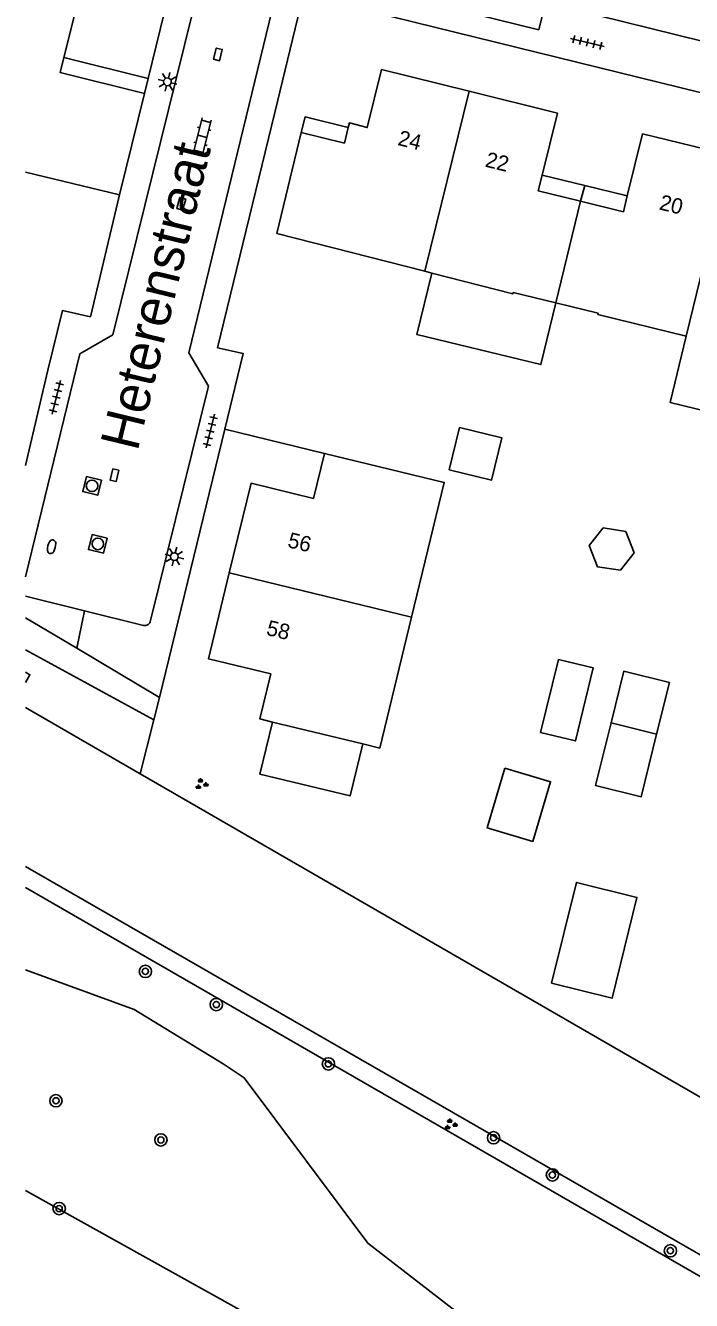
# Model space of a CAD drawing. Extents: x 128000 to 131008, y 398996 to 402500.
# Drawn here: x 128000 to 128043.1, y 399274.1 to 399356.7 of the extents above; entities that cross this region are included whole.
import ezdxf

# ---------------------------------------------------------------- set-up
doc = ezdxf.new("R2010")
doc.units = 0
for name, color, linetype in [('gg-afsc-erfafscheiding', 7, 'Continuous'), ('gg-afsc-muur', 7, 'Continuous'), ('gg-anno-huisnummerreeks BGT', 7, 'Continuous'), ('gg-anno-openbare ruimte label', 7, 'Continuous'), ('gg-bbg-gedigitaliseerde bebouwing', 7, 'Continuous'), ('gg-bbg-gedigitaliseerde bijgebouw', 7, 'Continuous'), ('gg-bbg-hoofdgebouw', 7, 'Continuous'), ('gg-bbg-luifel en loopbrug', 7, 'Continuous'), ('gg-bbg-tussenscheiding', 7, 'Continuous'), ('gg-knt-BGT kruinlijn', 7, 'Continuous'), ('gg-knt-bovenkant onderkant talud', 7, 'Continuous'), ('gg-knt-verharding', 7, 'Continuous'), ('gg-kntw-beschoeiing', 7, 'Continuous'), ('gg-kwrk-uitstroombak niveau min 01', 7, 'Continuous'), ('gt-grn-groengrens', 7, 'Continuous'), ('gt-grn-vlakafsluiter', 7, 'Continuous'), ('gt-grn-weggrens', 7, 'Continuous'), ('gt-symb-boom', 7, 'Continuous'), ('gt-symb-brandkraan', 7, 'Continuous'), ('gt-symb-groenvak', 7, 'Continuous'), ('gt-symb-klinker verharding', 7, 'Continuous'), ('gt-symb-kolk', 7, 'Continuous'), ('gt-symb-lichtmast', 7, 'Continuous'), ('gt-symb-rioolschacht', 7, 'Continuous'), ('gt-symb-tegel verharding', 7, 'Continuous')]:
    doc.layers.add(name, color=color, linetype=linetype)

# ---------------------------------------------------------------- blocks, each defined once
blk = doc.blocks.new('gt0-TEG1')
at = {"layer": 'gt-symb-tegel verharding'}
for p, q in [((-1.125, 0), (1.125, 0)), ((-0.9, -0.25), (-0.9, 0.25)), ((-0.45, -0.25), (-0.45, 0.25)), ((0, -0.25), (0, 0.25)), ((0.45, -0.25), (0.45, 0.25)), ((0.9, -0.25), (0.9, 0.25))]:
    blk.add_line(p, q, dxfattribs=at)
blk = doc.blocks.new('gt0-LMAST')
at = {"layer": 'gt-symb-lichtmast'}
for p, q in [((-0.182, 0.173), (-0.447, 0.438)), ((-0.005, 0.246), (-0.005, 0.621)), ((0.172, 0.173), (0.437, 0.438)), ((-0.255, -0.004), (-0.63, -0.004)), ((-0.182, -0.181), (-0.447, -0.446)), ((-0.005, -0.254), (-0.005, -0.629)), ((0.437, -0.446), (0.172, -0.181)), ((0.245, -0.004), (0.62, -0.004))]:
    blk.add_line(p, q, dxfattribs=at)
blk.add_circle((-0.005, -0.004), 0.25, dxfattribs=at)
blk = doc.blocks.new('gt0-KOLK')
at = {"layer": 'gt-symb-kolk'}
blk.add_lwpolyline([(0, 0), (0.375, 0), (0.375, 0.4), (-0.375, 0.4), (-0.375, 0), (0, 0)], dxfattribs=at)
blk = doc.blocks.new('gt0-KL1')
at = {"layer": 'gt-symb-klinker verharding'}
for p, q in [((-1.15, 0.3), (1.15, 0.3)), ((-1, -0.3), (-1, 0.3)), ((-0.5, 0.3), (-0.5, 0.45)), ((0, -0.3), (0, 0.3)), ((0.5, 0.3), (0.5, 0.45)), ((1, -0.3), (1, 0.3)), ((-1.15, -0.3), (1.15, -0.3)), ((-0.5, -0.45), (-0.5, -0.3)), ((0.5, -0.45), (0.5, -0.3))]:
    blk.add_line(p, q, dxfattribs=at)
blk = doc.blocks.new('gt0-BOOM')
at = {"layer": 'gt-symb-boom'}
for radius in [0.4, 0.2]:
    blk.add_circle((0, 0), radius, dxfattribs=at)
blk = doc.blocks.new('gt0-GRVAK')
at = {"layer": 'gt-symb-groenvak'}
for p, q in [((-0.11, 0.189), (-0.228, 0.24)), ((-0.182, 0.153), (0.088, 0.153)), ((-0.091, 0.211), (-0.156, 0.322)), ((-0.047, 0.214), (-0.047, 0.393)), ((-0.004, 0.211), (0.061, 0.322)), ((0.015, 0.189), (0.133, 0.24)), ((0.262, -0.052), (0.197, 0.059)), ((0.305, -0.049), (0.305, 0.13)), ((0.349, -0.052), (0.414, 0.059)), ((-0.245, -0.228), (-0.363, -0.177)), ((-0.318, -0.264), (-0.047, -0.264)), ((-0.226, -0.206), (-0.291, -0.095)), ((-0.183, -0.203), (-0.183, -0.024)), ((-0.139, -0.206), (-0.074, -0.095)), ((-0.12, -0.228), (-0.002, -0.177)), ((0.243, -0.074), (0.125, -0.023)), ((0.17, -0.11), (0.441, -0.11)), ((0.368, -0.074), (0.486, -0.023))]:
    blk.add_line(p, q, dxfattribs=at)
blk = doc.blocks.new('gt0-BR')
at = {"layer": 'gt-symb-brandkraan'}
for centre, radius, start, end in [((-0.244, 0), 0.206, 107.56694, 252.43307), ((0.599, -2.664), 3, 106.89205, 107.56694), ((0, -0.691), 0.938, 73.10799, 106.89205), ((-0.599, -2.664), 3, 72.43309, 73.10799), ((0.244, 0), 0.206, 287.56695, 72.43309), ((0.599, 2.664), 3, 252.43307, 253.10797), ((0, 0.691), 0.938, 253.10797, 286.89206), ((-0.599, 2.664), 3, 286.89206, 287.56695)]:
    blk.add_arc(centre, radius, start, end, dxfattribs=at)
blk = doc.blocks.new('gt0-RS')
at = {"layer": 'gt-symb-rioolschacht'}
blk.add_lwpolyline([(-0.5, -0.5), (0.5, -0.5), (0.5, 0.5), (-0.5, 0.5)], close=True, dxfattribs=at)
blk.add_circle((0, 0), 0.375, dxfattribs=at)

msp = doc.modelspace()

# ---------------------------------------------------------------- linework, layer by layer
at = {"layer": 'gg-afsc-erfafscheiding'}
for points in [[(128016.144, 399351.084), (128012.44, 399335.85), (128014.1, 399335.47), (128012.911, 399330.575)], [(128001.436, 399334.404), (128002.39, 399338.258), (128004.2, 399337.86), (128006.09, 399345.75)]]:
    msp.add_lwpolyline(points, dxfattribs=at)
at = {"layer": 'gg-afsc-muur'}
msp.add_line((128019.36, 399329.01), (128012.911, 399330.575), dxfattribs=at)
at = {"layer": 'gg-bbg-gedigitaliseerde bebouwing'}
for p, q in [((128000, 399347.234), (128006.09, 399345.75)), ((128025.864, 399340.807), (128016.27, 399343.26)), ((128026.311, 399340.693), (128025.864, 399340.807)), ((128015.18, 399311.8), (128015.995, 399311.602)), ((128015.995, 399311.602), (128021.844, 399310.181))]:
    msp.add_line(p, q, dxfattribs=at)
for points in [[(128034.355, 399338.752), (128031.588, 399339.427), (128031.569, 399339.349), (128026.311, 399340.693)], [(128042.8, 399336.612), (128037.083, 399338.005), (128037.101, 399338.083), (128034.355, 399338.752)], [(128042.8, 399336.612), (128041.751, 399332.306), (128046.011, 399331.268)], [(128025.007, 399318.4), (128027.126, 399327.124), (128019.36, 399329.01)], [(128021.844, 399310.181), (128022.946, 399309.914), (128025.007, 399318.4)]]:
    msp.add_lwpolyline(points, dxfattribs=at)
at = {"layer": 'gg-bbg-gedigitaliseerde bijgebouw'}
msp.add_line((128040.881, 399310.816), (128037.932, 399311.542), dxfattribs=at)
for points in [[(128027.45, 399327.94), (128028.117, 399330.68), (128030.857, 399330.013), (128030.19, 399327.273), (128027.45, 399327.94)], [(128037.419, 399324.195), (128036.514, 399323.036), (128037.052, 399321.65), (128038.536, 399321.452), (128039.426, 399322.569), (128038.884, 399323.94), (128037.419, 399324.195)], [(128034.519, 399315.663), (128036.769, 399315.116), (128035.62, 399310.383), (128033.369, 399310.93), (128034.519, 399315.663)], [(128037.932, 399311.542), (128038.757, 399314.89), (128041.706, 399314.163), (128040.881, 399310.816)]]:
    msp.add_lwpolyline(points, dxfattribs=at)
at = {"layer": 'gg-bbg-hoofdgebouw'}
for p, q in [((128007.711, 399352.329), (128006.09, 399345.75)), ((128016.27, 399343.26), (128017.864, 399349.8))]:
    msp.add_line(p, q, dxfattribs=at)
for points in [[(128002.491, 399354.65), (128003.48, 399358.64), (128000, 399359.5)], [(128007.711, 399352.329), (128002.25, 399353.679), (128002.491, 399354.65)], [(128028.749, 399352.469), (128023.07, 399353.87), (128022.14, 399350.12), (128020.98, 399350.42), (128020.907, 399350.121)], [(128033.471, 399347.04), (128034.46, 399351.06), (128028.749, 399352.469)], [(128020.907, 399350.121), (128020.661, 399349.11), (128017.864, 399349.8)], [(128045.639, 399348.319), (128039.97, 399349.71), (128038.981, 399345.69)], [(128035.961, 399345.344), (128033.219, 399346.016), (128033.471, 399347.04)], [(128038.981, 399345.69), (128038.729, 399344.666), (128035.961, 399345.344)], [(128019.36, 399329.01), (128018.65, 399326.09), (128014.61, 399327.07), (128013.203, 399321.272)], [(128013.203, 399321.272), (128011.85, 399315.7), (128015.89, 399314.72), (128015.18, 399311.8)]]:
    msp.add_lwpolyline(points, dxfattribs=at)
at = {"layer": 'gg-bbg-luifel en loopbrug'}
for p, q in [((128007.95, 399353.3), (128002.491, 399354.65)), ((128007.711, 399352.329), (128007.95, 399353.3)), ((128033.471, 399347.04), (128036.225, 399346.365)), ((128035.961, 399345.344), (128036.225, 399346.365)), ((128036.225, 399346.365), (128038.981, 399345.69))]:
    msp.add_line(p, q, dxfattribs=at)
for points in [[(128020.907, 399350.121), (128018.11, 399350.81), (128017.864, 399349.8)], [(128034.355, 399338.752), (128033.381, 399334.756), (128025.341, 399336.714), (128026.311, 399340.693)], [(128015.995, 399311.602), (128015.177, 399308.236), (128021.025, 399306.814), (128021.844, 399310.181)], [(128040.881, 399310.816), (128039.881, 399306.759), (128036.932, 399307.486), (128037.932, 399311.542)], [(128031.054, 399308.607), (128029.909, 399304.746), (128032.871, 399303.867), (128034.015, 399307.729), (128031.054, 399308.607)], [(128034.074, 399294.686), (128035.681, 399301.209), (128039.61, 399300.24), (128038.003, 399293.717), (128034.074, 399294.686)]]:
    msp.add_lwpolyline(points, dxfattribs=at)
at = {"layer": 'gg-bbg-tussenscheiding'}
for p, q in [((128025.864, 399340.807), (128028.749, 399352.469)), ((128042.8, 399336.612), (128045.639, 399348.319)), ((128034.355, 399338.752), (128035.961, 399345.344)), ((128013.203, 399321.272), (128025.007, 399318.4))]:
    msp.add_line(p, q, dxfattribs=at)
at = {"layer": 'gg-knt-BGT kruinlijn'}
msp.add_line((128000, 399316.29), (128008.318, 399311.742), dxfattribs=at)
at = {"layer": 'gg-knt-bovenkant onderkant talud'}
msp.add_line((128000, 399300.881), (128056.572, 399268.252), dxfattribs=at)
at = {"layer": 'gg-knt-verharding'}
for p, q in [((128009.749, 399360.698), (128007.95, 399353.3)), ((128018, 399358.72), (128016.144, 399351.084)), ((128075.07, 399344.66), (128018, 399358.72)), ((128043.919, 399355.694), (128033.694, 399358.214)), ((128000, 399328.219), (128001.436, 399334.404)), ((128012.911, 399330.575), (128008.69, 399313.2)), ((128000, 399319.766), (128003.819, 399318.813)), ((128000, 399318.361), (128003.328, 399316.385)), ((128003.819, 399318.813), (128007.64, 399317.86)), ((128008.69, 399313.2), (128003.328, 399316.385))]:
    msp.add_line(p, q, dxfattribs=at)
for points in [[(128000, 399321.019), (128003.53, 399335.46), (128005.66, 399336.69), (128011.333, 399359.666)], [(128033.694, 399358.214), (128033.247, 399356.45), (128026.665, 399358.062), (128027.096, 399359.839)], [(128008.1, 399318.179), (128011.86, 399333.37), (128010.57, 399335.52), (128016.16, 399358.488)]]:
    msp.add_lwpolyline(points, dxfattribs=at)
msp.add_arc((128007.72, 399318.236), 0.384, 257.95322, 351.52771, dxfattribs=at)
at = {"layer": 'gg-kntw-beschoeiing'}
for p, q in [((128000, 399312.539), (128007.427, 399308.249)), ((128007.427, 399308.249), (128057.284, 399279.447)), ((128000, 399302.245), (128057.219, 399269.29))]:
    msp.add_line(p, q, dxfattribs=at)
at = {"layer": 'gg-kwrk-uitstroombak niveau min 01'}
msp.add_lwpolyline([(128000, 399314.84), (128000.29, 399314.67), (128000, 399314.168)], dxfattribs=at)
at = {"layer": 'gt-grn-groengrens'}
msp.add_line((128000, 399281.249), (128015.597, 399272.571), dxfattribs=at)
msp.add_lwpolyline([(128000, 399295.546), (128007.037, 399292.979), (128012.797, 399289.459), (128014.157, 399288.552), (128022.184, 399277.832), (128027.891, 399273.405), (128043.438, 399264.818), (128051.744, 399260.514)], dxfattribs=at)
at = {"layer": 'gt-grn-vlakafsluiter'}
for p, q in [((128008.69, 399313.2), (128008.318, 399311.742)), ((128008.318, 399311.742), (128007.427, 399308.249))]:
    msp.add_line(p, q, dxfattribs=at)
at = {"layer": 'gt-grn-weggrens'}
msp.add_line((128003.328, 399316.385), (128003.819, 399318.813), dxfattribs=at)

# ---------------------------------------------------------------- block references
at = {"layer": 'gt-symb-boom'}
for p in [(128007.764, 399295.446), (128012.36, 399293.301), (128019.619, 399289.454), (128001.972, 399287.066), (128008.767, 399284.529), (128030.316, 399284.669), (128034.129, 399282.262), (128002.181, 399280.081), (128041.772, 399277.351)]:
    msp.add_blockref('gt0-BOOM', p, dxfattribs=at)
at = {"layer": 'gt-symb-brandkraan', "rotation": 76.11658196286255}
msp.add_blockref('gt0-BR', (128001.69, 399322.962), dxfattribs=at)
at = {"layer": 'gt-symb-groenvak'}
for p in [(128011.381, 399307.572), (128027.525, 399285.525)]:
    msp.add_blockref('gt0-GRVAK', p, dxfattribs=at)
at = {"layer": 'gt-symb-klinker verharding', "rotation": 76.11658196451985}
msp.add_blockref('gt0-KL1', (128011.457, 399349.549), dxfattribs=at)
at = {"layer": 'gt-symb-kolk'}
for p, rotation in [((128012.657, 399354.81), 76.22785456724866), ((128010.281, 399345.12), 74.86552497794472), ((128005.955, 399327.546), 76.11658196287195)]:
    msp.add_blockref('gt0-KOLK', p, dxfattribs=dict(at, rotation=rotation))
at = {"layer": 'gt-symb-lichtmast'}
for p, rotation in [((128009.193, 399353.086), 76.1165819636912), ((128009.641, 399322.325), 76.11658196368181)]:
    msp.add_blockref('gt0-LMAST', p, dxfattribs=dict(at, rotation=rotation))
at = {"layer": 'gt-symb-rioolschacht'}
for p, rotation in [((128004.311, 399326.903), -103.88341803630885), ((128004.684, 399323.144), 76.11658196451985)]:
    msp.add_blockref('gt0-RS', p, dxfattribs=dict(at, rotation=rotation))
at = {"layer": 'gt-symb-tegel verharding'}
for p, rotation in [((128036.389, 399355.627), -13.71646932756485), ((128001.995, 399332.644), 76.11658196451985), ((128011.974, 399330.452), 76.1165819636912)]:
    msp.add_blockref('gt0-TEG1', p, dxfattribs=dict(at, rotation=rotation))

# ---------------------------------------------------------------- texts
at = {"layer": 'gg-anno-huisnummerreeks BGT'}
for s, rotation, p in [('24', 346.1, (128024.059, 399348.992)), ('22', 346.1, (128029.723, 399347.595)), ('20', 346.2, (128040.995, 399344.824)), ('56', 346.4, (128016.925, 399322.941)), ('58', 346.4, (128015.545, 399317.256))]:
    msp.add_text(s, height=1, rotation=rotation, dxfattribs=at).set_placement(p)
at = {"layer": 'gg-anno-openbare ruimte label'}
msp.add_text('Heterenstraat', height=2.5, rotation=76.4, dxfattribs=at).set_placement((128007.258, 399329.088))

doc.saveas('drawing.dxf')
